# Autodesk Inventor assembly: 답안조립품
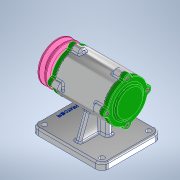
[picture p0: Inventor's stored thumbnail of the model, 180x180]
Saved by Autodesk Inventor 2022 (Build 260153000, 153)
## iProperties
Created: 2023-05
Part Number: 답안조립품
Document SubType Name: Assembly
Designer: Admin
Author: Admin
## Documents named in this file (12)
- C:\Users\Admin\Desktop\730508V1005\답안조립품.iam
- C:\Users\Admin\Desktop\730508V1005\본체.ipt
- C:\Users\Admin\Desktop\730508V1005\개스킷.ipt
- C:\Users\Admin\Desktop\730508V1005\앞커버.ipt
- C:\Users\Admin\Desktop\730508V1005\뒤커버.ipt
- C:\Users\Admin\Desktop\730508V1005\베어링 6204.ipt
- C:\Users\Admin\Desktop\730508V1005\오일 실.ipt
- C:\Users\Admin\Desktop\730508V1005\축.ipt
- C:\Users\Admin\Desktop\730508V1005\키 4 x 4.ipt
- C:\Users\Admin\Desktop\730508V1005\너트 M12 x 1.25.ipt
- C:\Users\Admin\Desktop\730508V1005\V-벨트풀리.ipt
- C:\Users\Admin\Desktop\730508V1005\볼트 M4 x 12.ipt
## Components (8 placed, 6 different names)
1. 개스킷:1
2. 개스킷:2
3. KS B 2023 6204 - 20 x 47 x 14:1
4. KS B 2023 6204 - 20 x 47 x 14:2
5. KS B 2804 D D - 20 32 8:1
6. KS B 1311 (I) 4 x 4 x 12:1
7. KS B 1012 클래스 1 일반 - 미터 M12x1.25:1
8. V-벨트풀리:1
